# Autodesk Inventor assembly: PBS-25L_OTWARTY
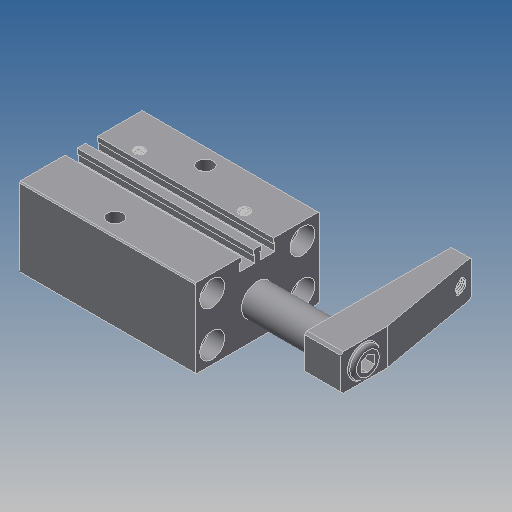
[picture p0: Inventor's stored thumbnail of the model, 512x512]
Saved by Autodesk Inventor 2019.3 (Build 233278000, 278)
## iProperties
Created: 2010-02
Part Number: PBS-25L_OTWARTY
Material: Ogólny
Document SubType Name: Assembly
Designer: CADENGINEERING4
Sending System: PRO/ENGINEER BY PARAMETRIC TECHNOLOGY CORPORATION, 2007170
Preprocessor: PRO/ENGINEER BY PARAMETRIC TECHNOLOGY CORPORATION, 2007170
Title: PSB-25_ASM
Author: Administrator
Revision Number: 1LAST_VERSION
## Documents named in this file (6)
- E:\SERWER_ZAPAS\Pneumatic\PSB PNEUMATIC SWING\PSB-25\PBS-25L_OTWARTY.iam
- E:\SERWER_ZAPAS\Pneumatic\PSB PNEUMATIC SWING\PSB-25\PSB-25BT.ipt
- E:\SERWER_ZAPAS\Pneumatic\PSB PNEUMATIC SWING\PSB-25\PSB-25HSG.ipt
- E:\SERWER_ZAPAS\Pneumatic\PSB PNEUMATIC SWING\PSB-25\PSB-25HG.ipt
- E:\SERWER_ZAPAS\Pneumatic\PSB PNEUMATIC SWING\PSB-25\PSB-25YB.ipt
- E:\SERWER_ZAPAS\Pneumatic\PSB PNEUMATIC SWING\PSB-25\M8X20.ipt
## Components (5 placed, 5 different names)
1. PSB-25BT_0 — Równoległe:1, Zestawiające:1, Zestawiające:2, Zestawiające:3, Kątowe:1
2. PSB-25HSG_1 — Zestawiające:2, Zestawiające:3, Zestawiające:4, Zestawiające:5
3. PSB-25HG_2 — Równoległe:1, Zestawiające:1
4. PSB-25YB_3 — Zestawiające:4, Zestawiające:5, Zestawiające:6, Zestawiające:7, Kątowe:1
5. M8X20_4 — Zestawiające:6, Zestawiające:7
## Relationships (9: Mate 7, Flush 1, Angle 1)
- Równoległe:1 [Flush]: PSB-25BT_0 ↔ PSB-25HG_2
- Zestawiające:1 [Mate]: PSB-25BT_0 ↔ PSB-25HG_2
- Zestawiające:2 [Mate]: PSB-25BT_0 ↔ PSB-25HSG_1
- Zestawiające:3 [Mate]: PSB-25BT_0 ↔ PSB-25HSG_1
- Zestawiające:4 [Mate]: PSB-25HSG_1 ↔ PSB-25YB_3
- Zestawiające:5 [Mate]: PSB-25HSG_1 ↔ PSB-25YB_3
- Zestawiające:6 [Mate]: PSB-25YB_3 ↔ M8X20_4
- Zestawiające:7 [Mate]: PSB-25YB_3 ↔ M8X20_4
- Kątowe:1 [Angle]: PSB-25BT_0 ↔ PSB-25YB_3
